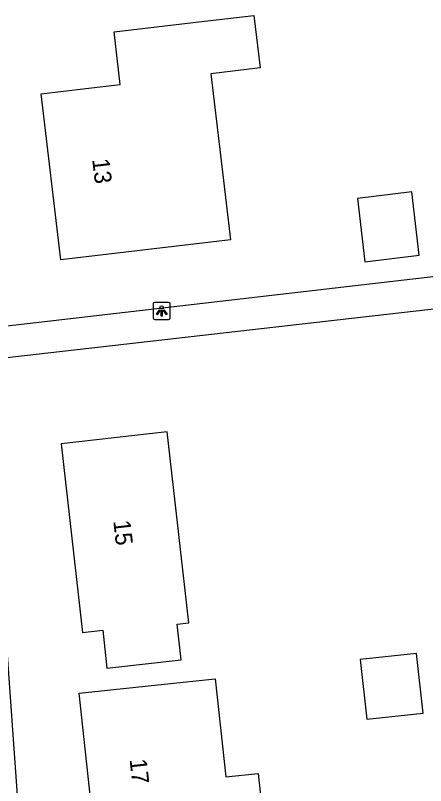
# Model space of a CAD drawing. Extents: x 162675 to 163482, y 379761 to 381227.
# Drawn here: x 163039.16 to 163063.15, y 380627.19 to 380672.29 of the extents above; entities that cross this region are included whole.
import ezdxf

# ---------------------------------------------------------------- set-up
doc = ezdxf.new("R2010")
doc.units = 0
for name, color, linetype in [('IMGEO_Lichtpunt', 7, 'Continuous'), ('IMGEO_Pand', 7, 'Continuous'), ('IMGEO_Pand_nummerreeks', 7, 'Continuous'), ('IMGEO_Voetpad_open', 7, 'Continuous')]:
    doc.layers.add(name, color=color, linetype=linetype)

msp = doc.modelspace()

# ---------------------------------------------------------------- linework, layer by layer
at = {"layer": 'IMGEO_Lichtpunt'}
for p, q in [((163047.216, 380655.389), (163047.216, 380654.582)), ((163047.216, 380655.389), (163047.216, 380654.582)), ((163048.118, 380655.484), (163047.31, 380655.484)), ((163048.118, 380655.484), (163047.31, 380655.484)), ((163048.212, 380654.582), (163048.212, 380655.389)), ((163048.212, 380654.582), (163048.212, 380655.389)), ((163047.31, 380654.488), (163048.118, 380654.488)), ((163047.31, 380654.488), (163048.118, 380654.488))]:
    msp.add_line(p, q, dxfattribs=at)
for points in [[(163047.59, 380655.053), (163047.629, 380655.025), (163047.441, 380654.763), (163047.403, 380654.79), (163047.59, 380655.053)], [(163047.692, 380655.005), (163047.739, 380655.005), (163047.739, 380654.683), (163047.692, 380654.683), (163047.692, 380655.005)], [(163047.802, 380655.025), (163047.84, 380655.052), (163048.027, 380654.79), (163047.988, 380654.762), (163047.802, 380655.025)]]:
    msp.add_lwpolyline(points, dxfattribs=at)
msp.add_circle((163047.715, 380655.187), 0.0994, dxfattribs=at)
for centre, start, end in [((163047.31, 380655.389), 90, 180), ((163047.31, 380655.389), 90, 180), ((163048.118, 380655.389), 0, 90), ((163048.118, 380655.389), 0, 90), ((163047.31, 380654.582), 180, 270), ((163047.31, 380654.582), 180, 270), ((163048.118, 380654.582), 270, 0), ((163048.118, 380654.582), 270, 360)]:
    msp.add_arc(centre, 0.0946, start, end, dxfattribs=at)
at = {"layer": 'IMGEO_Pand'}
for points in [[(163051.749, 380659.138), (163041.807, 380657.97), (163040.657, 380667.691), (163043.276, 380667.999), (163045.287, 380668.235), (163044.93, 380671.316), (163049.895, 380671.905), (163053.11, 380672.287), (163053.473, 380669.216), (163050.598, 380668.867), (163051.161, 380664.103), (163051.749, 380659.138)], [(163059.168, 380661.576), (163059.604, 380657.867), (163062.778, 380658.24), (163062.343, 380661.949), (163059.168, 380661.576)], [(163048.855, 380634.556), (163048.621, 380636.642), (163049.297, 380636.718), (163048.599, 380642.927), (163048.04, 380647.895), (163041.839, 380647.198), (163043.081, 380636.149), (163044.263, 380636.282), (163044.512, 380634.066), (163048.855, 380634.556)], [(163059.329, 380634.572), (163059.704, 380631.082), (163063.004, 380631.437), (163062.628, 380634.927), (163059.329, 380634.572)], [(163053.779, 380623.892), (163048.907, 380623.369), (163043.936, 380622.835), (163042.887, 380632.592), (163047.858, 380633.126), (163050.841, 380633.446), (163051.458, 380627.709), (163053.348, 380627.899), (163053.779, 380623.892)]]:
    msp.add_lwpolyline(points, dxfattribs=at)
at = {"layer": 'IMGEO_Voetpad_open'}
for points in [[(163064.055, 380657.039), (163063.757, 380657.004), (163037.315, 380653.943), (163032.944, 380715.524), (163058.632, 380719.002), (163058.898, 380719.038)], [(163067.753, 380591.633), (163041.973, 380588.769), (163037.446, 380652.111), (163063.957, 380655.14), (163064.179, 380655.165)]]:
    msp.add_lwpolyline(points, dxfattribs=at)

# ---------------------------------------------------------------- texts
at = {"layer": 'IMGEO_Pand_nummerreeks'}
for s, rotation, p in [('13', 276.7468, (163043.648, 380663.857)), ('15', 276.4136, (163044.882, 380642.686)), ('17', 276.1364, (163045.838, 380628.714))]:
    msp.add_text(s, height=1, rotation=rotation, dxfattribs=at).set_placement(p)

doc.saveas('drawing.dxf')
